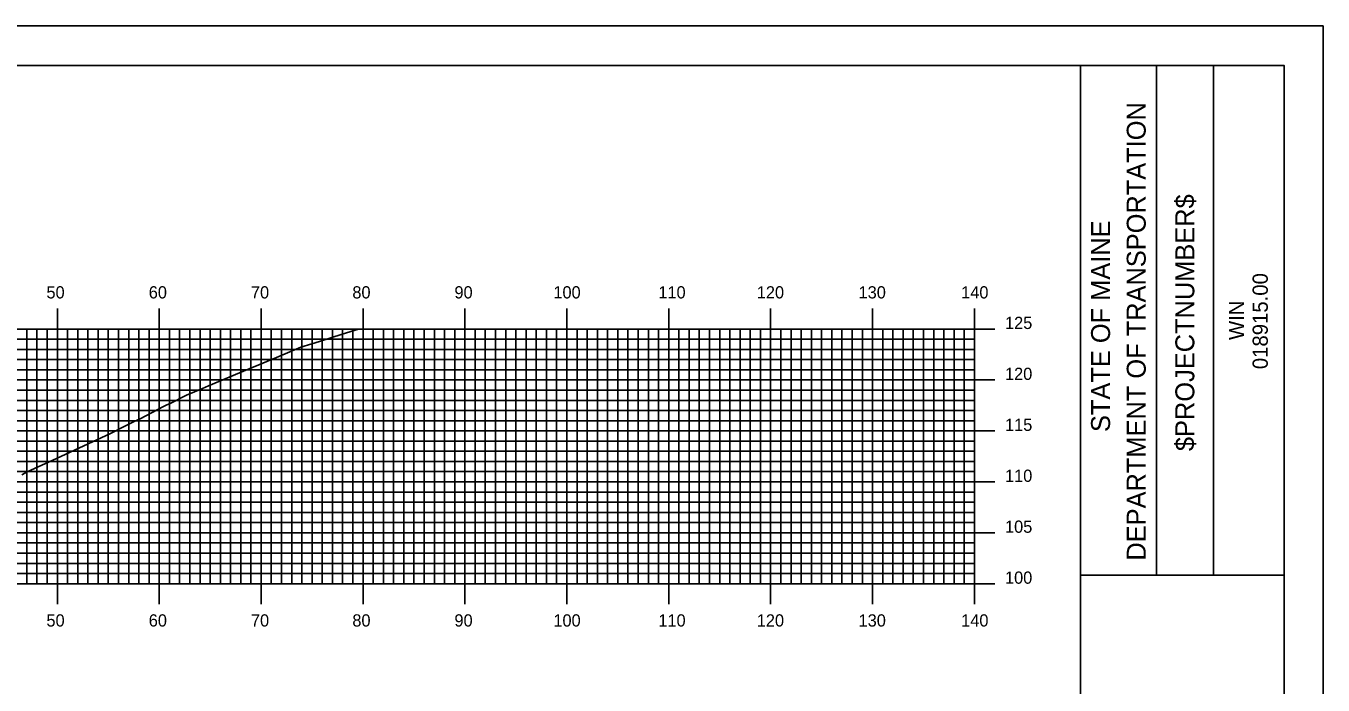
# Model space of a CAD drawing. Extents: x 1685192 to 1685536, y 461260 to 461480.
# Drawn here: x 1685405.1 to 1685532.4, y 461415.3 to 461480 of the extents above; entities that cross this region are included whole.
import ezdxf

# ---------------------------------------------------------------- set-up
doc = ezdxf.new("R2010")
doc.units = 0
for name, color, linetype in [('BORDER', 7, 'Continuous'), ('H_V ANNOTATION', 7, 'Continuous'), ('MAJOR', 7, 'Continuous'), ('MINOR', 7, 'Continuous'), ('PLOT BOUNDARY', 7, 'Continuous'), ('S_Roadway_Centerline', 7, 'Continuous')]:
    doc.layers.add(name, color=color, linetype=linetype)

msp = doc.modelspace()

# ---------------------------------------------------------------- linework, layer by layer
at = {"layer": 'BORDER'}
for p, q in [((1685508.63, 461266.07), (1685508.63, 461476.07)), ((1685516.09, 461426.07), (1685516.09, 461476.07)), ((1685521.68, 461426.07), (1685521.68, 461476.07)), ((1685508.63, 461426.06), (1685528.63, 461426.06))]:
    msp.add_line(p, q, dxfattribs=at)
msp.add_lwpolyline([(1685208.63, 461266.07), (1685528.63, 461266.07), (1685528.63, 461476.07), (1685208.63, 461476.07)], close=True, dxfattribs=at)
at = {"layer": 'MAJOR'}
for p, q in [((1685408.23, 461452.21), (1685408.23, 461450.21)), ((1685418.23, 461452.21), (1685418.23, 461450.21)), ((1685428.23, 461452.21), (1685428.23, 461450.21)), ((1685438.23, 461452.21), (1685438.23, 461450.21)), ((1685448.23, 461452.21), (1685448.23, 461450.21)), ((1685458.23, 461452.21), (1685458.23, 461450.21)), ((1685468.23, 461452.21), (1685468.23, 461450.21)), ((1685478.23, 461452.21), (1685478.23, 461450.21)), ((1685488.23, 461452.21), (1685488.23, 461450.21)), ((1685498.23, 461452.21), (1685498.23, 461450.21)), ((1685218.23, 461450.21), (1685498.23, 461450.21)), ((1685218.23, 461450.21), (1685498.23, 461450.21)), ((1685408.23, 461425.21), (1685408.23, 461450.21)), ((1685418.23, 461425.21), (1685418.23, 461450.21)), ((1685428.23, 461425.21), (1685428.23, 461450.21)), ((1685438.23, 461425.21), (1685438.23, 461450.21)), ((1685448.23, 461425.21), (1685448.23, 461450.21)), ((1685458.23, 461425.21), (1685458.23, 461450.21)), ((1685468.23, 461425.21), (1685468.23, 461450.21)), ((1685478.23, 461425.21), (1685478.23, 461450.21)), ((1685488.23, 461425.21), (1685488.23, 461450.21)), ((1685500.23, 461450.21), (1685496.23, 461450.21)), ((1685498.23, 461425.21), (1685498.23, 461450.21)), ((1685498.23, 461425.21), (1685498.23, 461450.21)), ((1685218.23, 461445.21), (1685498.23, 461445.21)), ((1685500.23, 461445.21), (1685496.23, 461445.21)), ((1685218.23, 461440.21), (1685498.23, 461440.21)), ((1685500.23, 461440.21), (1685496.23, 461440.21)), ((1685218.23, 461435.21), (1685498.23, 461435.21)), ((1685500.23, 461435.21), (1685496.23, 461435.21)), ((1685218.23, 461430.21), (1685498.23, 461430.21)), ((1685500.23, 461430.21), (1685496.23, 461430.21)), ((1685218.23, 461425.21), (1685498.23, 461425.21)), ((1685218.23, 461425.21), (1685498.23, 461425.21)), ((1685408.23, 461423.2), (1685408.23, 461425.21)), ((1685418.23, 461423.2), (1685418.23, 461425.21)), ((1685428.23, 461423.2), (1685428.23, 461425.21)), ((1685438.23, 461423.2), (1685438.23, 461425.21)), ((1685448.23, 461423.2), (1685448.23, 461425.21)), ((1685458.23, 461423.2), (1685458.23, 461425.21)), ((1685468.23, 461423.2), (1685468.23, 461425.21)), ((1685478.23, 461423.2), (1685478.23, 461425.21)), ((1685488.23, 461423.2), (1685488.23, 461425.21)), ((1685500.23, 461425.21), (1685496.23, 461425.21)), ((1685498.23, 461423.2), (1685498.23, 461425.21))]:
    msp.add_line(p, q, dxfattribs=at)
at = {"layer": 'MINOR'}
for p, q in [((1685218.23, 461449.21), (1685498.23, 461449.21)), ((1685405.23, 461425.21), (1685405.23, 461450.21)), ((1685406.23, 461425.21), (1685406.23, 461450.21)), ((1685407.23, 461425.21), (1685407.23, 461450.21)), ((1685409.23, 461425.21), (1685409.23, 461450.21)), ((1685410.23, 461425.21), (1685410.23, 461450.21)), ((1685411.23, 461425.21), (1685411.23, 461450.21)), ((1685412.23, 461425.21), (1685412.23, 461450.21)), ((1685413.23, 461425.21), (1685413.23, 461450.21)), ((1685414.23, 461425.21), (1685414.23, 461450.21)), ((1685415.23, 461425.21), (1685415.23, 461450.21)), ((1685416.23, 461425.21), (1685416.23, 461450.21)), ((1685417.23, 461425.21), (1685417.23, 461450.21)), ((1685419.23, 461425.21), (1685419.23, 461450.21)), ((1685420.23, 461425.21), (1685420.23, 461450.21)), ((1685421.23, 461425.21), (1685421.23, 461450.21)), ((1685422.23, 461425.21), (1685422.23, 461450.21)), ((1685423.23, 461425.21), (1685423.23, 461450.21)), ((1685424.23, 461425.21), (1685424.23, 461450.21)), ((1685425.23, 461425.21), (1685425.23, 461450.21)), ((1685426.23, 461425.21), (1685426.23, 461450.21)), ((1685427.23, 461425.21), (1685427.23, 461450.21)), ((1685429.23, 461425.21), (1685429.23, 461450.21)), ((1685430.23, 461425.21), (1685430.23, 461450.21)), ((1685431.23, 461425.21), (1685431.23, 461450.21)), ((1685432.23, 461425.21), (1685432.23, 461450.21)), ((1685433.23, 461425.21), (1685433.23, 461450.21)), ((1685434.23, 461425.21), (1685434.23, 461450.21)), ((1685435.23, 461425.21), (1685435.23, 461450.21)), ((1685436.23, 461425.21), (1685436.23, 461450.21)), ((1685437.23, 461425.21), (1685437.23, 461450.21)), ((1685439.23, 461425.21), (1685439.23, 461450.21)), ((1685440.23, 461425.21), (1685440.23, 461450.21)), ((1685441.23, 461425.21), (1685441.23, 461450.21)), ((1685442.23, 461425.21), (1685442.23, 461450.21)), ((1685443.23, 461425.21), (1685443.23, 461450.21)), ((1685444.23, 461425.21), (1685444.23, 461450.21)), ((1685445.23, 461425.21), (1685445.23, 461450.21)), ((1685446.23, 461425.21), (1685446.23, 461450.21)), ((1685447.23, 461425.21), (1685447.23, 461450.21)), ((1685449.23, 461425.21), (1685449.23, 461450.21)), ((1685450.23, 461425.21), (1685450.23, 461450.21)), ((1685451.23, 461425.21), (1685451.23, 461450.21)), ((1685452.23, 461425.21), (1685452.23, 461450.21)), ((1685453.23, 461425.21), (1685453.23, 461450.21)), ((1685454.23, 461425.21), (1685454.23, 461450.21)), ((1685455.23, 461425.21), (1685455.23, 461450.21)), ((1685456.23, 461425.21), (1685456.23, 461450.21)), ((1685457.23, 461425.21), (1685457.23, 461450.21)), ((1685459.23, 461425.21), (1685459.23, 461450.21)), ((1685460.23, 461425.21), (1685460.23, 461450.21)), ((1685461.23, 461425.21), (1685461.23, 461450.21)), ((1685462.23, 461425.21), (1685462.23, 461450.21)), ((1685463.23, 461425.21), (1685463.23, 461450.21)), ((1685464.23, 461425.21), (1685464.23, 461450.21)), ((1685465.23, 461425.21), (1685465.23, 461450.21)), ((1685466.23, 461425.21), (1685466.23, 461450.21)), ((1685467.23, 461425.21), (1685467.23, 461450.21)), ((1685469.23, 461425.21), (1685469.23, 461450.21)), ((1685470.23, 461425.21), (1685470.23, 461450.21)), ((1685471.23, 461425.21), (1685471.23, 461450.21)), ((1685472.23, 461425.21), (1685472.23, 461450.21)), ((1685473.23, 461425.21), (1685473.23, 461450.21)), ((1685474.23, 461425.21), (1685474.23, 461450.21)), ((1685475.23, 461425.21), (1685475.23, 461450.21)), ((1685476.23, 461425.21), (1685476.23, 461450.21)), ((1685477.23, 461425.21), (1685477.23, 461450.21)), ((1685479.23, 461425.21), (1685479.23, 461450.21)), ((1685480.23, 461425.21), (1685480.23, 461450.21)), ((1685481.23, 461425.21), (1685481.23, 461450.21)), ((1685482.23, 461425.21), (1685482.23, 461450.21)), ((1685483.23, 461425.21), (1685483.23, 461450.21)), ((1685484.23, 461425.21), (1685484.23, 461450.21)), ((1685485.23, 461425.21), (1685485.23, 461450.21)), ((1685486.23, 461425.21), (1685486.23, 461450.21)), ((1685487.23, 461425.21), (1685487.23, 461450.21)), ((1685489.23, 461425.21), (1685489.23, 461450.21)), ((1685490.23, 461425.21), (1685490.23, 461450.21)), ((1685491.23, 461425.21), (1685491.23, 461450.21)), ((1685492.23, 461425.21), (1685492.23, 461450.21)), ((1685493.23, 461425.21), (1685493.23, 461450.21)), ((1685494.23, 461425.21), (1685494.23, 461450.21)), ((1685495.23, 461425.21), (1685495.23, 461450.21)), ((1685496.23, 461425.21), (1685496.23, 461450.21)), ((1685498.23, 461449.21), (1685496.23, 461449.21)), ((1685497.23, 461425.21), (1685497.23, 461450.21)), ((1685218.23, 461448.21), (1685498.23, 461448.21)), ((1685498.23, 461448.21), (1685496.23, 461448.21)), ((1685218.23, 461447.21), (1685498.23, 461447.21)), ((1685498.23, 461447.21), (1685496.23, 461447.21)), ((1685218.23, 461446.21), (1685498.23, 461446.21)), ((1685498.23, 461446.21), (1685496.23, 461446.21)), ((1685218.23, 461444.21), (1685498.23, 461444.21)), ((1685498.23, 461444.21), (1685496.23, 461444.21)), ((1685218.23, 461443.21), (1685498.23, 461443.21)), ((1685498.23, 461443.21), (1685496.23, 461443.21)), ((1685218.23, 461442.21), (1685498.23, 461442.21)), ((1685498.23, 461442.21), (1685496.23, 461442.21)), ((1685218.23, 461441.21), (1685498.23, 461441.21)), ((1685498.23, 461441.21), (1685496.23, 461441.21)), ((1685218.23, 461439.21), (1685498.23, 461439.21)), ((1685498.23, 461439.21), (1685496.23, 461439.21)), ((1685218.23, 461438.21), (1685498.23, 461438.21)), ((1685498.23, 461438.21), (1685496.23, 461438.21)), ((1685218.23, 461437.21), (1685498.23, 461437.21)), ((1685498.23, 461437.21), (1685496.23, 461437.21)), ((1685218.23, 461436.21), (1685498.23, 461436.21)), ((1685498.23, 461436.21), (1685496.23, 461436.21)), ((1685218.23, 461434.21), (1685498.23, 461434.21)), ((1685498.23, 461434.21), (1685496.23, 461434.21)), ((1685218.23, 461433.21), (1685498.23, 461433.21)), ((1685498.23, 461433.21), (1685496.23, 461433.21)), ((1685218.23, 461432.21), (1685498.23, 461432.21)), ((1685218.23, 461431.21), (1685498.23, 461431.21)), ((1685498.23, 461432.21), (1685496.23, 461432.21)), ((1685498.23, 461431.21), (1685496.23, 461431.21)), ((1685218.23, 461429.21), (1685498.23, 461429.21)), ((1685498.23, 461429.21), (1685496.23, 461429.21)), ((1685218.23, 461428.21), (1685498.23, 461428.21)), ((1685498.23, 461428.21), (1685496.23, 461428.21)), ((1685218.23, 461427.21), (1685498.23, 461427.21)), ((1685218.23, 461426.21), (1685498.23, 461426.21)), ((1685498.23, 461427.21), (1685496.23, 461427.21)), ((1685498.23, 461426.21), (1685496.23, 461426.21))]:
    msp.add_line(p, q, dxfattribs=at)
at = {"layer": 'PLOT BOUNDARY'}
msp.add_lwpolyline([(1685192.44, 461259.95), (1685532.44, 461259.95), (1685532.44, 461479.95), (1685192.44, 461479.95)], close=True, dxfattribs=at)
at = {"layer": 'S_Roadway_Centerline'}
msp.add_lwpolyline([(1685404.75, 461435.9), (1685405.28, 461436.18), (1685408.14, 461437.5), (1685411.24, 461438.93), (1685413.44, 461439.95), (1685414.86, 461440.67), (1685415.7, 461441.09), (1685416.35, 461441.41), (1685418.66, 461442.59), (1685418.99, 461442.76), (1685419.24, 461442.88), (1685420.89, 461443.72), (1685422.46, 461444.37), (1685423.08, 461444.63), (1685426.1, 461445.9), (1685428.4, 461446.87), (1685429.74, 461447.43), (1685432.13, 461448.43), (1685433.19, 461448.77), (1685433.95, 461449), (1685436.18, 461449.71), (1685437.79, 461450.21)], dxfattribs=at)

# ---------------------------------------------------------------- texts
at = {"layer": 'BORDER'}
for s, height, p in [('DEPARTMENT OF TRANSPORTATION', 1.8635, (1685515.04, 461427.48)), ('$PROJECTNUMBER$', 1.8635, (1685519.81, 461438.23)), ('STATE OF MAINE', 1.8635, (1685511.54, 461440.1)), ('018915.00', 1.491, (1685527.02, 461446.27)), ('WIN', 1.491, (1685524.7, 461449.13))]:
    msp.add_text(s, height=height, rotation=90, dxfattribs=at).set_placement(p)
at = {"layer": 'H_V ANNOTATION'}
for s, p in [('50', (1685407.16, 461453.21)), ('60', (1685417.2, 461453.21)), ('70', (1685427.23, 461453.21)), ('80', (1685437.18, 461453.21)), ('90', (1685447.2, 461453.21)), ('100', (1685456.91, 461453.21)), ('110', (1685467.21, 461453.21)), ('120', (1685476.87, 461453.21)), ('130', (1685486.86, 461453.21)), ('140', (1685496.93, 461453.21)), ('125', (1685501.23, 461450.21)), ('120', (1685501.23, 461445.21)), ('115', (1685501.23, 461440.21)), ('110', (1685501.23, 461435.21)), ('105', (1685501.23, 461430.21)), ('100', (1685501.23, 461425.21)), ('50', (1685407.16, 461421.01)), ('60', (1685417.2, 461421.01)), ('70', (1685427.23, 461421.01)), ('80', (1685437.18, 461421.01)), ('90', (1685447.2, 461421.01)), ('100', (1685456.91, 461421.01)), ('110', (1685467.21, 461421.01)), ('120', (1685476.87, 461421.01)), ('130', (1685486.86, 461421.01)), ('140', (1685496.93, 461421.01))]:
    msp.add_text(s, height=1.2, dxfattribs=at).set_placement(p)

doc.saveas('drawing.dxf')
